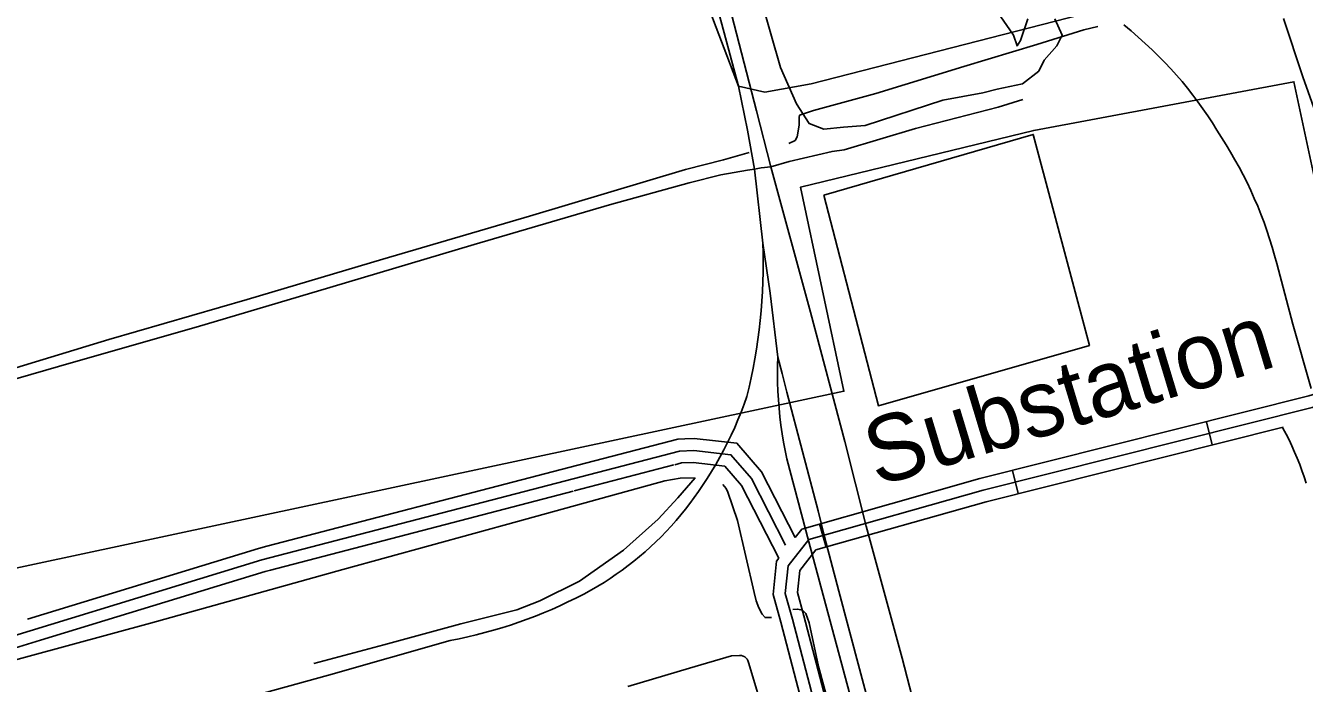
# Model space of a CAD drawing. Extents: x 3419139 to 3457078, y 540382 to 565875.
# Drawn here: x 3439733 to 3441333, y 561238 to 562061 of the extents above; entities that cross this region are included whole.
import ezdxf

# ---------------------------------------------------------------- set-up
doc = ezdxf.new("R2010")
doc.units = 0
for name, color, linetype in [('V-RAIL-TRAK', 7, 'Continuous'), ('V-ROAD-CNTR', 7, 'Continuous'), ('V-SITE-OTLN', 7, 'Continuous'), ('V-SITE-OTLN-IDEN', 7, 'Continuous'), ('V-SITE-VEGE', 7, 'Continuous'), ('V-TOPO-SHOR', 7, 'Continuous')]:
    doc.layers.add(name, color=color, linetype=linetype)

msp = doc.modelspace()

# ---------------------------------------------------------------- linework, layer by layer
at = {"layer": 'V-RAIL-TRAK'}
for points in [[(3440600.5, 562134.9), (3440647.3, 561954), (3440665.4, 561883.8), (3440715, 561702.1), (3440757.9, 561540.4), (3440784.6, 561434.4), (3440829.6, 561269.3), (3440878.4, 561080.7), (3440923.4, 560918.3), (3440984.3, 560682.3), (3441031.2, 560507.5), (3441089.5, 560288), (3441147.1, 560071.2), (3441183.2, 559928.8), (3441202, 559862.2), (3441233.6, 559749.3)], [(3440590.7, 562112.3), (3440624.9, 561985), (3440636.2, 561930), (3440644.8, 561881.2), (3440655.1, 561788.4), (3440664.3, 561725.8), (3440674.1, 561646), (3440679.5, 561625.3), (3440685.5, 561602), (3440724.3, 561453.4), (3440732.4, 561421), (3440750.4, 561352.9), (3440790, 561204.3), (3440836.2, 561034.3), (3440877.7, 560874), (3440913.9, 560739.8), (3440952.1, 560599.4), (3440995, 560437), (3441030.5, 560297.3), (3441064, 560175.5), (3441106.9, 560013.8), (3441145.1, 559872.7), (3441188.6, 559707.6), (3441201.4, 559660.9)], [(3441106.7, 562061.5), (3441115.8, 562053.9), (3441124.7, 562046.1), (3441133.5, 562038.3), (3441142.1, 562030.2), (3441150.6, 562022), (3441158.1, 562014.4), (3441165.4, 562006.5), (3441172.5, 561998.6), (3441179.5, 561990.5), (3441186.2, 561982.2), (3441192.9, 561973.8), (3441199.3, 561965.2), (3441205.5, 561956.6), (3441211.6, 561947.8), (3441217.5, 561938.8), (3441223.2, 561929.8), (3441228.7, 561920.6), (3441234.5, 561911.5), (3441240.2, 561902.2), (3441245.6, 561892.9), (3441250.8, 561883.4), (3441255.9, 561873.9), (3441260.8, 561864.2), (3441265.4, 561854.4), (3441269.9, 561844.5), (3441274.1, 561834.6), (3441278.1, 561824.6), (3441282, 561814.4), (3441285.6, 561804.2)], [(3441285.6, 561804.2), (3441289, 561794), (3441292.2, 561783.6), (3441295.2, 561773.2), (3441297.9, 561762.8), (3441318, 561687.1), (3441340.8, 561606.5)], [(3440655.1, 561788.4), (3440655.5, 561776.3), (3440655.6, 561764.2), (3440655.5, 561752.1), (3440655.2, 561740), (3440654.7, 561727.9), (3440654, 561715.9), (3440653.1, 561703.8), (3440651.9, 561691.8), (3440650.6, 561679.8), (3440649, 561667.8), (3440647.3, 561655.8), (3440645.3, 561643.9), (3440643.1, 561632), (3440640.7, 561620.1), (3440638.1, 561608.3), (3440635.3, 561596.6), (3440631.9, 561586.8), (3440628.1, 561577.1), (3440624.2, 561567.4), (3440620.1, 561557.9), (3440615.8, 561548.4), (3440611.2, 561539.1), (3440606.5, 561529.8), (3440601.5, 561520.7), (3440596.4, 561511.6), (3440591, 561502.7), (3440585.5, 561493.9), (3440579.8, 561485.2), (3440574.7, 561477.6), (3440569.4, 561470.1), (3440564, 561462.7), (3440558.4, 561455.5), (3440552.6, 561448.4), (3440546.7, 561441.4), (3440540.6, 561434.5), (3440534.4, 561427.8), (3440528, 561421.2), (3440521.5, 561414.8), (3440514.8, 561408.5), (3440508, 561402.4), (3440501.1, 561396.4), (3440494, 561390.6), (3440486.8, 561385), (3440479.5, 561379.5), (3440472, 561374.1), (3440464.5, 561369), (3440456.8, 561364), (3440449, 561359.2), (3440441.1, 561354.6), (3440431.3, 561349.3), (3440421.5, 561344.3), (3440411.5, 561339.5), (3440401.5, 561334.8), (3440391.3, 561330.3), (3440381.1, 561326), (3440370.8, 561321.9), (3440360.5, 561318), (3440350, 561314.2), (3440339.6, 561310.7), (3440329, 561307.3), (3440318.4, 561304.2), (3440307.7, 561301.2), (3440297, 561298.4), (3440286.2, 561295.9), (3440275.4, 561293.5), (3440264.5, 561291.3), (3440112.1, 561247.8), (3439941.1, 561200.9)], [(3440685.4, 561518.5), (3440683.2, 561528.9), (3440681.2, 561539.5), (3440679.5, 561550), (3440678, 561560.6), (3440676.7, 561571.2), (3440675.6, 561581.9), (3440674.8, 561592.6), (3440674.2, 561603.2), (3440673.8, 561613.9), (3440673.7, 561624.6), (3440673.8, 561635.3), (3440674.1, 561646)], [(3441201.4, 559660.9), (3441183.8, 559696), (3441169.6, 559731), (3441137.4, 559825.1), (3441100.5, 559954.3), (3441055.7, 560121.1), (3441017.6, 560265.3), (3440980.2, 560405.4), (3440938.1, 560570.2), (3440890, 560752.8), (3440849.2, 560906), (3440811.8, 561047.4), (3440769, 561205.3), (3440712.8, 561414.8), (3440685.4, 561518.5)]]:
    msp.add_lwpolyline(points, dxfattribs=at)
at = {"layer": 'V-ROAD-CNTR'}
for p, q in [((3441209.9, 561565.1), (3441217.2, 561536)), ((3440967.4, 561504.2), (3440974.7, 561475.1)), ((3440726.2, 561437.1), (3440734.4, 561408.2))]:
    msp.add_line(p, q, dxfattribs=at)
for points in [[(3438815.6, 561351.5), (3438839.2, 561357.5), (3438976.2, 561397.1), (3439101.5, 561435.4), (3439297.6, 561493.2), (3439491, 561550.9), (3439632.8, 561593.3), (3439793.2, 561639.6), (3439946.7, 561683.2), (3440113.9, 561732.9), (3440294.2, 561786.6), (3440463.6, 561836.3), (3440563.3, 561863.8), (3440602.6, 561873.9), (3440636.3, 561879.8), (3440644.8, 561881.2), (3440653, 561882.5), (3440665.4, 561883.8), (3440688.1, 561890.5), (3440741.8, 561903.2), (3440756.9, 561905.1), (3440846.4, 561932), (3440949.6, 561958.8), (3440980.6, 561968.2)], [(3441978.6, 561774.9), (3441342.1, 561582.9), (3440930.7, 561479.5), (3440712.9, 561417.7), (3440686.9, 561384.8), (3440683.2, 561350.3), (3440692.2, 561318.2), (3440785.3, 560962.3), (3440786.9, 560908.2)], [(3440695.7, 561420.1), (3440704.2, 561430.8), (3440926.8, 561494), (3441338.1, 561597.3), (3441493, 561644.1)], [(3440801.6, 560916.9), (3440800.3, 560964.4), (3440706.7, 561322.1), (3440698.5, 561351.5), (3440701.4, 561378.9), (3440721.7, 561404.6), (3440934.6, 561465), (3441305.9, 561558.3)], [(3441305.1, 561558.1), (3441305.7, 561557), (3441309.6, 561549.6), (3441313.4, 561542.2), (3441316.9, 561534.7), (3441320.3, 561527.1), (3441323.5, 561519.4), (3441326.6, 561511.7), (3441329.4, 561503.8), (3441332.1, 561496), (3441334.6, 561488)], [(3440557.8, 561543.6), (3440548.9, 561543.2), (3440403.1, 561505.2)], [(3440695.7, 561420.1), (3440653.7, 561502.2), (3440622.8, 561538), (3440569.4, 561544.1), (3440557.8, 561543.6)], [(3440683.8, 561410.5), (3440641.2, 561493.8), (3440615.3, 561523.8), (3440568.8, 561529.1), (3440551.2, 561528.3), (3440028.8, 561392.1), (3439609.5, 561263.9), (3439593.4, 561233.1), (3439584.7, 561187.7), (3439581.2, 561142.3), (3439563.6, 561117.5), (3439539.5, 561096.6)], [(3440543.8, 561510.9), (3440419.5, 561478.4)], [(3440675.3, 561394.2), (3440628.7, 561485.4), (3440607.7, 561509.5), (3440568.3, 561514), (3440553.4, 561513.4), (3440545.2, 561511.2)], [(3440403.1, 561505.2), (3440034.9, 561409.2)], [(3440418.1, 561478.1), (3440039.6, 561379.4)], [(3440034.9, 561409.2), (3440024.7, 561406.5), (3439735.9, 561318.2)], [(3440768.3, 560967.9), (3440677.7, 561314.3), (3440668, 561349), (3440672.5, 561390.7), (3440675.3, 561394.2)], [(3440039.6, 561379.4), (3440032.9, 561377.6), (3439752.1, 561291.8)], [(3439752.1, 561291.8), (3439643.3, 561258.5)]]:
    msp.add_lwpolyline(points, dxfattribs=at)
at = {"layer": 'V-SITE-OTLN'}
for p, q in [((3440624.9, 561985), (3440492.8, 562332.7)), ((3441052.2, 562074.1), (3440715.7, 561987.8)), ((3440657.7, 561977.2), (3440624.9, 561985)), ((3440715.7, 561987.8), (3440657.7, 561977.2))]:
    msp.add_line(p, q, dxfattribs=at)
for points in [[(3441215.1, 559326.2), (3441157, 559313.7), (3440359, 559142.1), (3440035.7, 559073.3), (3439387.2, 558935.4), (3438963.4, 560917.5), (3438901.6, 561206.6), (3440756.7, 561603.2), (3440702.2, 561858.4), (3440994.1, 561929.6), (3441319.4, 561990.3), (3441403.1, 561599), (3441739.1, 560028.5), (3441741.8, 560014.4), (3441372, 559935.4), (3441469.3, 559480.5), (3441489.7, 559384.9)], [(3440731.4, 561848.3), (3440993.4, 561924.6), (3441063.6, 561660.2), (3440799.8, 561585)]]:
    msp.add_lwpolyline(points, close=True, dxfattribs=at)
at = {"layer": 'V-SITE-VEGE'}
for points in [[(3441020.6, 562069.2), (3441029.7, 562048.8), (3441022.9, 562035.2), (3441007.1, 562017.2), (3441000.3, 562003.6), (3440980, 561987.8), (3440948.3, 561981), (3440930.2, 561976.5), (3440880.5, 561967.4), (3440783.4, 561935.8), (3440756.3, 561933.5), (3440731.4, 561931.2), (3440713.4, 561938), (3440697.5, 561962.9), (3440677.2, 562008.1), (3440604.9, 562261.3)], [(3440948.3, 562078.2), (3440968.7, 562048.8), (3440973.2, 562035.2), (3440977.7, 562042), (3440986.7, 562069.2)]]:
    msp.add_lwpolyline(points, dxfattribs=at)
at = {"layer": 'V-TOPO-SHOR'}
for points in [[(3440688, 561913.1), (3440695.6, 561916.8), (3440698.4, 561921.6), (3440700.6, 561936), (3440700.6, 561945.6), (3440701.3, 561948.4), (3440718.5, 561954.4), (3440796.4, 561975.9), (3440906.5, 562009.5), (3440998.1, 562037.1), (3441056.7, 562055.2), (3441074.1, 562059.7)], [(3441443, 561793.8), (3441420.5, 561811.2), (3441401.3, 561836.7), (3441378.9, 561871.8), (3441370.5, 561885.8), (3441365.8, 561897.1), (3441360, 561913.8), (3441348.5, 561945.9), (3441330.6, 561996.5), (3441306.4, 562069.6)], [(3439093.9, 561449.4), (3439267.4, 561499.1), (3439408.6, 561539.4), (3439537.4, 561578.3), (3439701.9, 561626.7), (3439837.6, 561667.7), (3440010.4, 561718.1), (3440179.9, 561768.4), (3440363.7, 561822.2), (3440558.6, 561880.6), (3440606.1, 561892.7), (3440638.4, 561901.7)], [(3439633.3, 561243.4), (3439889.6, 561313), (3440130.1, 561380), (3440348.6, 561440.2), (3440532.7, 561491), (3440552, 561494.3), (3440570.5, 561494.9)], [(3440093.7, 561262.6), (3440181.2, 561285.7), (3440277.5, 561312.2), (3440347.5, 561329.6), (3440376.3, 561340.8), (3440426, 561365.6), (3440481.1, 561404.4), (3440524.2, 561443.2), (3440548.9, 561469.9), (3440570.5, 561494.9)], [(3440605.4, 561486.4), (3440609.5, 561481.6), (3440611.7, 561476.8), (3440623.4, 561441.3), (3440644.5, 561351.3), (3440646.9, 561340.8), (3440650.3, 561332.3), (3440654.4, 561324.2), (3440658.2, 561319.9), (3440661.6, 561319.9), (3440666, 561320.1)], [(3440692.8, 561329.9), (3440698.7, 561330.6), (3440704.9, 561329.2), (3440709, 561325), (3440713.3, 561313.6), (3440724.8, 561258.6), (3440742.6, 561194.3), (3440754.7, 561153.7), (3440764.5, 561120.3), (3440778.4, 561050), (3440794.1, 560993.7), (3440801.7, 560977.8), (3440809.6, 560964.7), (3440814.5, 560963.5), (3440822.1, 560965)], [(3440486.4, 561233.8), (3440563.4, 561256.8), (3440616.1, 561272), (3440625.9, 561272.6), (3440628.6, 561272.6), (3440632.7, 561270.8), (3440634.6, 561269.4), (3440635.9, 561267.8), (3440636.6, 561266.4), (3440637.9, 561262.7)], [(3440637.9, 561262.7), (3440663.4, 561177.3)]]:
    msp.add_lwpolyline(points, dxfattribs=at)

# ---------------------------------------------------------------- texts
at = {"layer": 'V-SITE-OTLN-IDEN'}
msp.add_text('Substation', height=83, rotation=16.7853, dxfattribs=at).set_placement((3440797.7, 561483.6))

doc.saveas('drawing.dxf')
